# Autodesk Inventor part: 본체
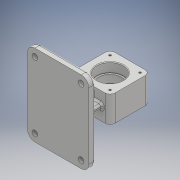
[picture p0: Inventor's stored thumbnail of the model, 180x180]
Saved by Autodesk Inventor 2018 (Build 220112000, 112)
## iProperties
Created: 2020-11
Part Number: 본체
Material: Generic
Document SubType Name: Modeling
Designer: Administrator
Density: 1 g/cm^3
Appearance: Default
Author: Administrator
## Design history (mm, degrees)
sketch "스케치4"
  geometry: L1 (-32, 32)-(32, 32); L2 (32, 32)-(32, -32); L3 (32, -32)-(-32, -32); L4 (-32, -32)-(-32, 32); L5 (-32, 32)-(32, -32); L6 (32, 32)-(-32, -32); 1 further point
  constraints: 12 end point, 2 midpoint, 2 parallel, 1 horizontal, 1 perpendicular
  dimensions: "d6" = 64 distance of L2.end L3.end; "d7" = 64 distance of L1.end L2.end
extrude "돌출2" new body sketch "스케치4" stored distance "d8" = 42; taper "d9" = 0 deg
sketch "스케치5"
  geometry: L1 (32, 21)-(-32, 21) reference; L2 (0, 21)-(21, 21); L3 (21, 21)-(21, 6); L4 (21, 6)-(0, 6); L5 (0, 6)-(0, 21); L6 (0, 6)-(18, 6); L7 (18, 6)-(18, -6); L8 (18, -6)-(0, -6); L9 (0, -6)-(0, 6); L10 (-32, -21)-(32, -21) reference; L11 (0, -6)-(21, -6); L12 (21, -6)-(21, -21); L13 (21, -21)-(0, -21); L14 (0, -21)-(0, -6); 1 further point
  constraints: 24 end point, 6 parallel, 3 horizontal, 3 perpendicular, 2 point on line, 1 midpoint
  dimensions: "d10" = 42 diameter of L3 L5; "d11" = 36 diameter of L7 L9; "d12" = 15 distance of L2.end L3.end; "d13" = 15 distance of L11.end L12.end
revolve "회전1" sketch "스케치5" stored, may be unused: angle "d14" = 90 deg
node "작업 평면1"
sketch "스케치6"
  geometry: L1 (62, 65)-(-36, 65); L2 (-36, 65)-(-36, -65); L3 (-36, -65)-(62, -65); L4 (62, -65)-(62, 65); L5 (62, 65)-(-36, -65); L6 (-36, 65)-(62, -65); L7 (32, -21)-(32, 21) reference; L8 (-32, 21)-(32, 21) reference; L9 (-32, 21)-(-32, -21) reference; L10 (32, -21)-(-32, -21) reference; 3 further points
  constraints: 12 end point, 3 midpoint, 2 parallel, 1 horizontal, 1 horizontal alignment, 1 perpendicular
  dimensions: "d16" = 130 distance of L1.end L2.end; "d17" = 98 distance of L2.end L3.end; "d18" = 62 distance from line of point (0, 0) L4
extrude "돌출3" join sketch "스케치6" distance "d19" = 10; taper "d20" = 0 deg
sketch "스케치7"
  geometry: L1 (-4, -17)-(4, -17); L2 (4, -17)-(4, 17); L3 (4, 17)-(-4, 17); L4 (-4, 17)-(-4, -17); L5 (-4, -17)-(4, 17); L6 (4, -17)-(-4, 17); L7 (20, 4)-(-20, 4); L8 (-20, 4)-(-20, -4); L9 (-20, -4)-(20, -4); L10 (20, -4)-(20, 4); L11 (20, 4)-(-20, -4); L12 (-20, 4)-(20, -4); 1 further point
  constraints: 24 end point, 4 midpoint, 4 parallel, 2 horizontal, 2 perpendicular
  dimensions: "d21" = 8 distance of L3.end L2.end; "d22" = 34 distance of L2.end L1.end; "d23" = 40 distance of L9.end L8.end; "d24" = 8 distance of L8.end L7.end
extrude "돌출4" join sketch "스케치7" stored distance "d25" = 10; taper "d26" = 0 deg
fillet "모깎기1" dims "d27" = 12
fillet "모깎기2" dims "d28" = 3
fillet "모깎기3" dims "d29" = 3
fillet "모깎기4" dims "d30" = 8
sketch "스케치8"
  geometry: L1 (-24, 24)-(24, 24); L2 (24, 24)-(24, -24); L3 (24, -24)-(-24, -24); L4 (-24, -24)-(-24, 24); L5 (-24, 24)-(24, -24); L6 (24, 24)-(-24, -24); 2 further points
  constraints: 12 end point, 2 midpoint, 2 parallel, 1 coincident, 1 horizontal, 1 perpendicular
  dimensions: "d31" = 48 distance of L2.end L3.end; "d32" = 48 distance of L1.end L2.end
hole "구멍1" sketch "스케치8" at (-24, 24) diameter "d33" = 3.242; stored, may be unused: countersink angle "d37" = 90 deg, drill point angle "d39" = 118 deg; dims "d34" = 8, "d35" = 4, "d36" = 2, "d38" = 10
sketch "스케치9"
  geometry: L1 (-24, 24)-(24, 24); L2 (24, 24)-(24, -24); L3 (24, -24)-(-24, -24); L4 (-24, -24)-(-24, 24); L5 (-24, 24)-(24, -24); L6 (24, 24)-(-24, -24); 2 further points
  constraints: 12 end point, 2 midpoint, 2 parallel, 1 coincident, 1 horizontal, 1 perpendicular
  dimensions: "d43" = 48 distance of L2.end L3.end; "d44" = 48 distance of L1.end L2.end
hole "구멍2" sketch "스케치9" at (-24, 24) diameter "d45" = 3.242; stored, may be unused: countersink angle "d49" = 90 deg, drill point angle "d51" = 118 deg; dims "d46" = 8, "d47" = 4, "d48" = 2, "d50" = 10
sketch "스케치10"
  geometry: C1 r 4.5 at (24, 53); C2 r 4.5 at (-50, 53); A1 r 12 centre (24, 53) between (36, 53) and (24, 65) reference; A2 r 12 centre (-50, 53) between (-50, 65) and (-62, 53) reference; 1 further point
  constraints: 2 centre point, 2 coincident
  dimensions: "d55" = 4.5 radius of C1; "d56" = 4.5 radius of C2
extrude "돌출5" cut sketch "스케치10" extent not by distance; stored distance "d57" = 10; taper "d58" = 0 deg
fillet "모깎기5" dims "d59" = 0.3
fillet "모깎기6" dims "d60" = 1
sketch "스케치14"
  geometry: L1 (24, 65)-(-50, 65) reference; L2 (-62, 53)-(-62, -53) reference; 2 further points
  constraints: 1 other
  dimensions: "d61" = 65 distance from line of L1 point (-52, 0); "d62" = 10 distance from line of L2 point (-52, 0)
feature "엠보싱1" sketch "스케치14" dims "d6" = 64, "d7" = 64, "d12" = 15, "d63" = 0.5, "d64" = 0
node "솔리드2"
pattern_circular "원형 패턴1" dims angle "d41" = 360 deg
pattern_circular "원형 패턴2" dims angle "d53" = 360 deg
mirror "미러1"
node "투영된 루프1"
